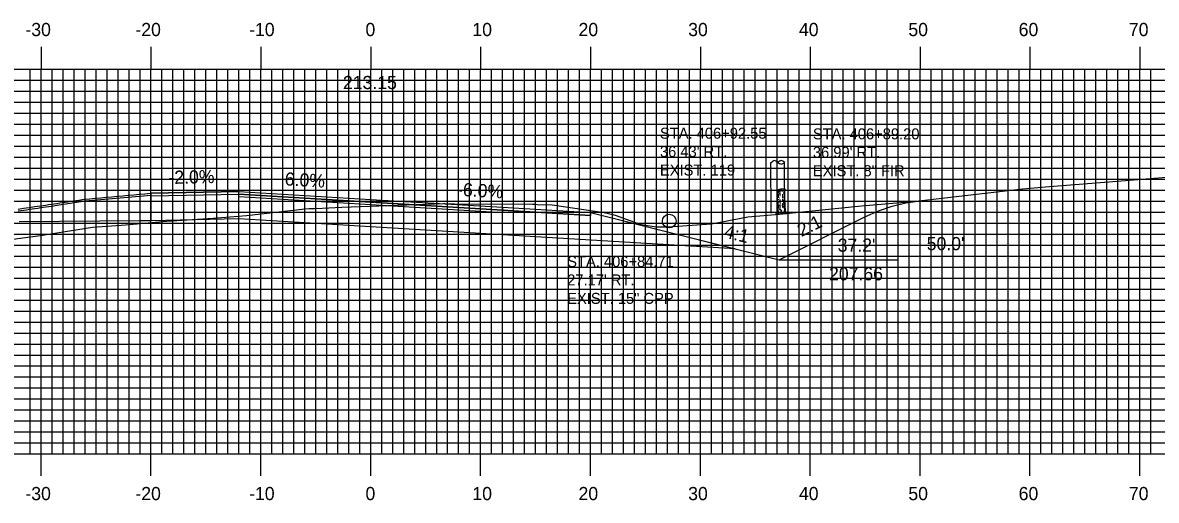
# Model space of a CAD drawing. Extents: x 852135 to 852479, y 364785 to 365005.
# Drawn here: x 852269.5 to 852372.7, y 364904 to 364947.5 of the extents above; entities that cross this region are included whole.
import ezdxf

# ---------------------------------------------------------------- set-up
doc = ezdxf.new("R2010")
doc.units = 0
for name, color, linetype in [('ANNOTATION', 7, 'Continuous'), ('D_Roadway_Centerline', 7, 'Continuous'), ('D_Roadway_Centerline_Text', 7, 'Continuous'), ('D_Roadway_Drive_Paved_LT', 7, 'Continuous'), ('D_Roadway_Drive_SubGrade', 7, 'Continuous'), ('D_Roadway_Edge_Shoulder', 7, 'Continuous'), ('D_Roadway_Edge_TW', 7, 'Continuous'), ('D_Roadway_Pavement', 7, 'Continuous'), ('D_Roadway_SlopeLines', 7, 'Continuous'), ('D_Roadway_SubGrade', 7, 'Continuous'), ('D_Text_Monospaced', 7, 'Continuous'), ('D_Text_Standard', 7, 'Continuous'), ('H_V ANNOTATION', 7, 'Continuous'), ('MAJOR', 7, 'Continuous'), ('MINOR', 7, 'Continuous'), ('PDRAIN', 7, 'Continuous'), ('S_Roadway_Centerline', 7, 'Continuous'), ('S_Trees_Conifer_NonPay', 7, 'Continuous'), ('S_Utilities_Pole_Power', 7, 'Continuous')]:
    doc.layers.add(name, color=color, linetype=linetype)

msp = doc.modelspace()

# ---------------------------------------------------------------- linework, layer by layer
at = {"layer": 'ANNOTATION'}
msp.add_line((852281.22, 364931.94), (852281.22, 364929.44), dxfattribs=at)
at = {"layer": 'D_Roadway_Centerline'}
for points in [[(852281.22, 364931.94), (852289.22, 364932.1), (852301.22, 364931.38), (852313.22, 364930.66), (852321.22, 364930.18), (852334.38, 364926.89), (852338.38, 364925.89), (852346.18, 364929.8), (852347.43, 364930.35), (852348.68, 364930.78), (852349.93, 364931.08), (852351.18, 364931.24)], [(852269.12, 364930.49), (852269.62, 364930.57), (852269.63, 364930.57), (852269.86, 364930.6), (852269.87, 364930.6), (852270.13, 364930.64), (852270.14, 364930.64), (852270.64, 364930.72), (852270.64, 364930.72), (852270.89, 364930.75), (852270.89, 364930.75), (852271.15, 364930.79), (852271.15, 364930.79), (852271.65, 364930.87), (852271.65, 364930.87), (852271.9, 364930.91), (852271.9, 364930.91), (852272.15, 364930.94), (852272.15, 364930.94), (852272.65, 364931.02), (852272.65, 364931.02), (852272.91, 364931.06), (852273.15, 364931.09), (852273.65, 364931.17), (852274.15, 364931.24), (852274.65, 364931.32), (852275.15, 364931.39), (852275.22, 364931.4), (852275.65, 364931.44), (852276.15, 364931.49), (852276.65, 364931.53), (852277.15, 364931.58), (852277.65, 364931.62), (852278.15, 364931.67), (852278.65, 364931.71), (852279.15, 364931.76), (852279.65, 364931.8), (852280.15, 364931.85), (852280.65, 364931.89), (852281.15, 364931.94), (852281.22, 364931.94)]]:
    msp.add_lwpolyline(points, dxfattribs=at)
at = {"layer": 'D_Roadway_Drive_Paved_LT'}
msp.add_lwpolyline([(852269.14, 364930.33), (852269.64, 364930.4), (852269.65, 364930.4), (852269.88, 364930.44), (852269.89, 364930.44), (852270.15, 364930.48), (852270.16, 364930.48), (852270.66, 364930.55), (852270.66, 364930.55), (852270.91, 364930.59), (852270.91, 364930.59), (852271.17, 364930.63), (852271.17, 364930.63), (852271.67, 364930.7), (852271.67, 364930.7), (852271.92, 364930.74), (852271.92, 364930.74), (852272.17, 364930.78), (852272.17, 364930.78), (852272.67, 364930.85), (852272.67, 364930.85), (852275.24, 364931.24), (852281.23, 364931.78)], dxfattribs=at)
at = {"layer": 'D_Roadway_Drive_SubGrade'}
for p, q in [((852280.22, 364929.42), (852269.22, 364929.33)), ((852281.22, 364929.44), (852280.22, 364929.42))]:
    msp.add_line(p, q, dxfattribs=at)
at = {"layer": 'D_Roadway_Edge_Shoulder'}
for points in [[(852289.22, 364932.1), (852281.22, 364931.94), (852281.22, 364931.69), (852289.22, 364931.85)], [(852313.22, 364930.66), (852321.22, 364930.18), (852321.22, 364929.93), (852313.22, 364930.41)]]:
    msp.add_lwpolyline(points, close=True, dxfattribs=at)
at = {"layer": 'D_Roadway_Edge_TW'}
msp.add_lwpolyline([(852289.22, 364931.85), (852289.22, 364932.1), (852301.22, 364931.38), (852313.22, 364930.66), (852313.22, 364930.41), (852301.22, 364931.13)], close=True, dxfattribs=at)
at = {"layer": 'D_Roadway_Pavement'}
msp.add_lwpolyline([(852289.22, 364931.6), (852289.22, 364931.85), (852301.22, 364931.13), (852313.22, 364930.41), (852313.22, 364930.16), (852301.22, 364930.88)], close=True, dxfattribs=at)
at = {"layer": 'D_Roadway_SlopeLines'}
for points in [[(852338.38, 364925.89), (852346.18, 364929.8), (852347.43, 364930.35), (852348.68, 364930.78), (852349.93, 364931.08), (852351.18, 364931.24)], [(852321.22, 364930.18), (852338.38, 364925.89)]]:
    msp.add_lwpolyline(points, dxfattribs=at)
at = {"layer": 'D_Roadway_SubGrade'}
msp.add_lwpolyline([(852289.22, 364929.6), (852281.22, 364929.44), (852281.22, 364931.94), (852281.22, 364931.69), (852289.22, 364931.85), (852301.22, 364931.13), (852313.22, 364930.41), (852321.22, 364929.93), (852321.22, 364930.18), (852334.38, 364926.89), (852313.22, 364928.16), (852301.22, 364928.88)], close=True, dxfattribs=at)
at = {"layer": 'MAJOR'}
for p, q in [((852271.22, 364945.24), (852271.22, 364943.23)), ((852281.22, 364945.24), (852281.22, 364943.23)), ((852291.22, 364945.24), (852291.22, 364943.23)), ((852301.22, 364945.24), (852301.22, 364943.23)), ((852311.22, 364945.24), (852311.22, 364943.23)), ((852321.22, 364945.24), (852321.22, 364943.23)), ((852331.22, 364945.24), (852331.22, 364943.23)), ((852341.22, 364945.24), (852341.22, 364943.23)), ((852351.22, 364945.24), (852351.22, 364943.23)), ((852361.22, 364945.24), (852361.22, 364943.23)), ((852371.22, 364945.24), (852371.22, 364943.23)), ((852161.22, 364943.23), (852441.22, 364943.23)), ((852161.22, 364943.23), (852441.22, 364943.23)), ((852271.22, 364908.23), (852271.22, 364943.23)), ((852281.22, 364908.23), (852281.22, 364943.23)), ((852291.22, 364908.23), (852291.22, 364943.23)), ((852301.22, 364908.23), (852301.22, 364943.23)), ((852311.22, 364908.23), (852311.22, 364943.23)), ((852321.22, 364908.23), (852321.22, 364943.23)), ((852331.22, 364908.23), (852331.22, 364943.23)), ((852341.22, 364908.23), (852341.22, 364943.23)), ((852351.22, 364908.23), (852351.22, 364943.23)), ((852361.22, 364908.23), (852361.22, 364943.23)), ((852371.22, 364908.23), (852371.22, 364943.23)), ((852161.22, 364938.23), (852441.22, 364938.23)), ((852161.22, 364933.23), (852441.22, 364933.23)), ((852161.22, 364928.23), (852441.22, 364928.23)), ((852161.22, 364923.23), (852441.22, 364923.23)), ((852161.22, 364918.23), (852441.22, 364918.23)), ((852161.22, 364913.23), (852441.22, 364913.23)), ((852161.22, 364908.23), (852441.22, 364908.23)), ((852161.22, 364908.23), (852441.22, 364908.23)), ((852271.22, 364906.23), (852271.22, 364908.23)), ((852281.22, 364906.23), (852281.22, 364908.23)), ((852291.22, 364906.23), (852291.22, 364908.23)), ((852301.22, 364906.23), (852301.22, 364908.23)), ((852311.22, 364906.23), (852311.22, 364908.23)), ((852321.22, 364906.23), (852321.22, 364908.23)), ((852331.22, 364906.23), (852331.22, 364908.23)), ((852341.22, 364906.23), (852341.22, 364908.23)), ((852351.22, 364906.23), (852351.22, 364908.23)), ((852361.22, 364906.23), (852361.22, 364908.23)), ((852371.22, 364906.23), (852371.22, 364908.23))]:
    msp.add_line(p, q, dxfattribs=at)
at = {"layer": 'MINOR'}
for p, q in [((852270.22, 364908.23), (852270.22, 364943.23)), ((852272.22, 364908.23), (852272.22, 364943.23)), ((852273.22, 364908.23), (852273.22, 364943.23)), ((852274.22, 364908.23), (852274.22, 364943.23)), ((852275.22, 364908.23), (852275.22, 364943.23)), ((852276.22, 364908.23), (852276.22, 364943.23)), ((852277.22, 364908.23), (852277.22, 364943.23)), ((852278.22, 364908.23), (852278.22, 364943.23)), ((852279.22, 364908.23), (852279.22, 364943.23)), ((852280.22, 364908.23), (852280.22, 364943.23)), ((852282.22, 364908.23), (852282.22, 364943.23)), ((852283.22, 364908.23), (852283.22, 364943.23)), ((852284.22, 364908.23), (852284.22, 364943.23)), ((852285.22, 364908.23), (852285.22, 364943.23)), ((852286.22, 364908.23), (852286.22, 364943.23)), ((852287.22, 364908.23), (852287.22, 364943.23)), ((852288.22, 364908.23), (852288.22, 364943.23)), ((852289.22, 364908.23), (852289.22, 364943.23)), ((852290.22, 364908.23), (852290.22, 364943.23)), ((852292.22, 364908.23), (852292.22, 364943.23)), ((852293.22, 364908.23), (852293.22, 364943.23)), ((852294.22, 364908.23), (852294.22, 364943.23)), ((852295.22, 364908.23), (852295.22, 364943.23)), ((852296.22, 364908.23), (852296.22, 364943.23)), ((852297.22, 364908.23), (852297.22, 364943.23)), ((852298.22, 364908.23), (852298.22, 364943.23)), ((852299.22, 364908.23), (852299.22, 364943.23)), ((852300.22, 364908.23), (852300.22, 364943.23)), ((852302.22, 364908.23), (852302.22, 364943.23)), ((852303.22, 364908.23), (852303.22, 364943.23)), ((852304.22, 364908.23), (852304.22, 364943.23)), ((852305.22, 364908.23), (852305.22, 364943.23)), ((852306.22, 364908.23), (852306.22, 364943.23)), ((852307.22, 364908.23), (852307.22, 364943.23)), ((852308.22, 364908.23), (852308.22, 364943.23)), ((852309.22, 364908.23), (852309.22, 364943.23)), ((852310.22, 364908.23), (852310.22, 364943.23)), ((852312.22, 364908.23), (852312.22, 364943.23)), ((852313.22, 364908.23), (852313.22, 364943.23)), ((852314.22, 364908.23), (852314.22, 364943.23)), ((852315.22, 364908.23), (852315.22, 364943.23)), ((852316.22, 364908.23), (852316.22, 364943.23)), ((852317.22, 364908.23), (852317.22, 364943.23)), ((852318.22, 364908.23), (852318.22, 364943.23)), ((852319.22, 364908.23), (852319.22, 364943.23)), ((852320.22, 364908.23), (852320.22, 364943.23)), ((852322.22, 364908.23), (852322.22, 364943.23)), ((852323.22, 364908.23), (852323.22, 364943.23)), ((852324.22, 364908.23), (852324.22, 364943.23)), ((852325.22, 364908.23), (852325.22, 364943.23)), ((852326.22, 364908.23), (852326.22, 364943.23)), ((852327.22, 364908.23), (852327.22, 364943.23)), ((852328.22, 364908.23), (852328.22, 364943.23)), ((852329.22, 364908.23), (852329.22, 364943.23)), ((852330.22, 364908.23), (852330.22, 364943.23)), ((852332.22, 364908.23), (852332.22, 364943.23)), ((852333.22, 364908.23), (852333.22, 364943.23)), ((852334.22, 364908.23), (852334.22, 364943.23)), ((852335.22, 364908.23), (852335.22, 364943.23)), ((852336.22, 364908.23), (852336.22, 364943.23)), ((852337.22, 364908.23), (852337.22, 364943.23)), ((852338.22, 364908.23), (852338.22, 364943.23)), ((852339.22, 364908.23), (852339.22, 364943.23)), ((852340.22, 364908.23), (852340.22, 364943.23)), ((852342.22, 364908.23), (852342.22, 364943.23)), ((852343.22, 364908.23), (852343.22, 364943.23)), ((852344.22, 364908.23), (852344.22, 364943.23)), ((852345.22, 364908.23), (852345.22, 364943.23)), ((852346.22, 364908.23), (852346.22, 364943.23)), ((852347.22, 364908.23), (852347.22, 364943.23)), ((852348.22, 364908.23), (852348.22, 364943.23)), ((852349.22, 364908.23), (852349.22, 364943.23)), ((852350.22, 364908.23), (852350.22, 364943.23)), ((852352.22, 364908.23), (852352.22, 364943.23)), ((852353.22, 364908.23), (852353.22, 364943.23)), ((852354.22, 364908.23), (852354.22, 364943.23)), ((852355.22, 364908.23), (852355.22, 364943.23)), ((852356.22, 364908.23), (852356.22, 364943.23)), ((852357.22, 364908.23), (852357.22, 364943.23)), ((852358.22, 364908.23), (852358.22, 364943.23)), ((852359.22, 364908.23), (852359.22, 364943.23)), ((852360.22, 364908.23), (852360.22, 364943.23)), ((852362.22, 364908.23), (852362.22, 364943.23)), ((852363.22, 364908.23), (852363.22, 364943.23)), ((852364.22, 364908.23), (852364.22, 364943.23)), ((852365.22, 364908.23), (852365.22, 364943.23)), ((852366.22, 364908.23), (852366.22, 364943.23)), ((852367.22, 364908.23), (852367.22, 364943.23)), ((852368.22, 364908.23), (852368.22, 364943.23)), ((852369.22, 364908.23), (852369.22, 364943.23)), ((852370.22, 364908.23), (852370.22, 364943.23)), ((852372.22, 364908.23), (852372.22, 364943.23)), ((852161.22, 364942.23), (852441.22, 364942.23)), ((852161.22, 364941.23), (852441.22, 364941.23)), ((852161.22, 364940.23), (852441.22, 364940.23)), ((852161.22, 364939.23), (852441.22, 364939.23)), ((852161.22, 364937.23), (852441.22, 364937.23)), ((852161.22, 364936.23), (852441.22, 364936.23)), ((852161.22, 364935.23), (852441.22, 364935.23)), ((852161.22, 364934.23), (852441.22, 364934.23)), ((852161.22, 364932.23), (852441.22, 364932.23)), ((852161.22, 364931.23), (852441.22, 364931.23)), ((852161.22, 364930.23), (852441.22, 364930.23)), ((852161.22, 364929.23), (852441.22, 364929.23)), ((852161.22, 364927.23), (852441.22, 364927.23)), ((852161.22, 364926.23), (852441.22, 364926.23)), ((852161.22, 364925.23), (852441.22, 364925.23)), ((852161.22, 364924.23), (852441.22, 364924.23)), ((852161.22, 364922.23), (852441.22, 364922.23)), ((852161.22, 364921.23), (852441.22, 364921.23)), ((852161.22, 364920.23), (852441.22, 364920.23)), ((852161.22, 364919.23), (852441.22, 364919.23)), ((852161.22, 364917.23), (852441.22, 364917.23)), ((852161.22, 364916.23), (852441.22, 364916.23)), ((852161.22, 364915.23), (852441.22, 364915.23)), ((852161.22, 364914.23), (852441.22, 364914.23)), ((852161.22, 364912.23), (852441.22, 364912.23)), ((852161.22, 364911.23), (852441.22, 364911.23)), ((852161.22, 364910.23), (852441.22, 364910.23)), ((852161.22, 364909.23), (852441.22, 364909.23))]:
    msp.add_line(p, q, dxfattribs=at)
at = {"layer": 'PDRAIN'}
msp.add_line((852338.38, 364925.89), (852349.15, 364925.89), dxfattribs=at)
at = {"layer": 'S_Roadway_Centerline'}
msp.add_lwpolyline([(852256.11, 364926.11), (852270.92, 364928.07), (852271.12, 364928.11), (852271.36, 364928.14), (852271.71, 364928.2), (852275.89, 364928.86), (852278.94, 364929.08), (852282.62, 364929.4), (852286.88, 364929.67), (852289.9, 364929.92), (852295.26, 364930.52), (852295.63, 364930.56), (852296.23, 364930.56), (852298.59, 364930.66), (852307.87, 364931), (852307.95, 364931.01), (852308.83, 364930.98), (852315.94, 364930.95), (852316.13, 364930.96), (852316.17, 364930.95), (852316.36, 364930.91), (852317.74, 364930.9), (852322.45, 364930.19), (852323.25, 364930.02), (852323.57, 364929.93), (852325.81, 364929.09), (852327.24, 364928.9), (852328.26, 364928.9), (852332.23, 364929.17), (852335.55, 364929.81), (852338.41, 364930.04), (852345.87, 364930.79), (852349.1, 364931.08), (852350.59, 364931.18), (852360.55, 364932.35), (852363.01, 364932.56), (852369.15, 364933.04), (852376.64, 364933.64)], dxfattribs=at)
at = {"layer": 'S_Trees_Conifer_NonPay'}
for p, q in [((852338.29, 364932.13), (852338.29, 364931.92)), ((852338.7, 364932.19), (852338.7, 364932.11)), ((852338.27, 364931.03), (852338.27, 364930.93)), ((852338.29, 364931.85), (852338.29, 364931.52)), ((852338.29, 364931.41), (852338.29, 364931.33)), ((852338.29, 364931.21), (852338.29, 364931.1)), ((852338.44, 364932.01), (852338.44, 364931.73)), ((852338.44, 364931.38), (852338.44, 364931.06)), ((852338.48, 364931.02), (852338.48, 364930.95)), ((852338.7, 364931.86), (852338.7, 364931.53)), ((852338.7, 364931.43), (852338.7, 364931.28)), ((852338.7, 364931.05), (852338.7, 364930.82)), ((852338.84, 364931.9), (852338.84, 364931.77)), ((852338.84, 364931.66), (852338.84, 364931.43)), ((852338.84, 364931.34), (852338.84, 364930.96)), ((852338.29, 364930.82), (852338.29, 364930.55)), ((852338.44, 364930.89), (852338.44, 364930.73)), ((852338.44, 364930.67), (852338.44, 364930.54)), ((852338.7, 364930.75), (852338.7, 364930.67)), ((852338.82, 364930.77), (852338.84, 364930.52)), ((852338.9, 364930.54), (852338.96, 364930.55))]:
    msp.add_line(p, q, dxfattribs=at)
for points in [[(852338.21, 364932.16), (852338.21, 364930.45), (852338.14, 364930.19), (852338.02, 364930.16), (852338.23, 364930.14), (852338.39, 364930.08), (852338.6, 364930.14), (852338.87, 364930.09), (852339.07, 364930.1), (852338.92, 364930.2), (852338.85, 364930.35)], [(852338.84, 364932.23), (852338.84, 364932.13), (852338.84, 364931.96)], [(852338.95, 364930.18), (852339.07, 364930.19), (852338.97, 364930.32), (852338.94, 364930.86), (852338.92, 364931.37), (852338.92, 364932.29)], [(852338.23, 364930.14), (852338.32, 364930.25), (852338.34, 364930.37)], [(852338.37, 364930.5), (852338.35, 364930.46), (852338.41, 364930.45), (852338.41, 364930.51)], [(852338.6, 364930.14), (852338.56, 364930.32), (852338.55, 364930.48)], [(852338.56, 364930.37), (852338.63, 364930.36), (852338.64, 364930.41)]]:
    msp.add_lwpolyline(points, dxfattribs=at)
for centre, radius, start, end in [((852338.27, 364932.13), 0.0729, 130.3798, 141.6195), ((852338.23, 364932.16), 0.0263, 141.6195, 160.3798), ((852338.23, 364932.16), 0.0186, 160.3798, 174.3267), ((852338.22, 364932.16), 0.0141, 174.3267, 190.3798), ((852338.22, 364932.16), 0.0141, 190.3798, 206.433), ((852338.23, 364932.17), 0.0186, 206.433, 220.3798), ((852338.23, 364932.17), 0.0263, 220.3798, 239.1402), ((852338.22, 364932.05), 0.0143, 180, 196.0515), ((852338.38, 364932), 0.245, 108.3946, 130.3798), ((852338.25, 364932.21), 0.0729, 239.1402, 250.3798), ((852338.31, 364932.37), 0.245, 250.3798, 272.3651), ((852338.88, 364930.5), 1.83, 100.3798, 108.3946), ((852338.25, 364933.95), 1.83, 272.3651, 280.3798), ((852338.88, 364930.5), 1.83, 92.3651, 100.3798), ((852338.25, 364933.95), 1.83, 280.3798, 288.3946), ((852338.81, 364932.08), 0.245, 70.3798, 92.3651), ((852338.75, 364932.45), 0.245, 288.3946, 310.3798), ((852338.78, 364932.24), 0.245, 291.7653, 300), ((852338.87, 364932.24), 0.0729, 59.1402, 70.3798), ((852338.86, 364932.09), 0.0738, 300, 311.2506), ((852338.9, 364932.28), 0.0263, 40.3798, 59.1402), ((852338.86, 364932.32), 0.0729, 310.3798, 321.6195), ((852338.89, 364932.29), 0.0263, 321.6195, 340.3798), ((852338.9, 364932.05), 0.0267, 311.2506, 330), ((852338.91, 364932.29), 0.0141, 10.3798, 26.433), ((852338.9, 364932.29), 0.0186, 26.433, 40.3798), ((852338.9, 364932.29), 0.0186, 340.3798, 354.3267), ((852338.91, 364932.29), 0.0141, 354.3267, 10.3798), ((852338.9, 364932.05), 0.0189, 330, 343.9485), ((852338.22, 364931.58), 0.0143, 180, 196.0515), ((852338.23, 364931.58), 0.0189, 196.0515, 210), ((852338.23, 364931.59), 0.0267, 210, 228.7494), ((852338.22, 364931.37), 0.0143, 180, 196.0515), ((852338.23, 364931.37), 0.0189, 196.0515, 210), ((852338.23, 364931.38), 0.0267, 210, 228.7494), ((852338.26, 364931.62), 0.0738, 228.7494, 240), ((852338.26, 364931.41), 0.0738, 228.7494, 240), ((852338.35, 364931.77), 0.245, 240, 246.7914), ((852338.35, 364931.56), 0.245, 240, 254.9514), ((852338.35, 364931.98), 0.245, 244.3148, 257.5375), ((852338.35, 364932.24), 0.245, 254.8461, 261.8968), ((852338.35, 364931.77), 0.245, 254.8461, 257.5454), ((852338.35, 364931.34), 0.245, 254.9814, 261.8968), ((852338.56, 364932.85), 1.77, 261.8968, 262.45), ((852338.56, 364933.74), 1.77, 261.8968, 262.605), ((852338.56, 364933.74), 1.77, 264.3267, 266.0499), ((852338.56, 364933.28), 1.77, 265.2285, 266.1325), ((852338.57, 364933.49), 1.77, 265.8991, 267.5962), ((852338.56, 364933.07), 1.77, 266.0429, 268.5525), ((852338.57, 364933.49), 1.77, 272.7221, 274.4847), ((852338.56, 364933.07), 1.77, 274.5361, 277.0026), ((852338.56, 364933.74), 1.77, 276.2449, 278.1032), ((852338.56, 364932.85), 1.77, 276.7966, 278.1032), ((852338.78, 364932.24), 0.245, 278.1032, 284.1859), ((852338.78, 364931.34), 0.245, 278.1032, 284.3207), ((852338.78, 364931.77), 0.245, 284.1859, 300), ((852338.78, 364931.56), 0.245, 292.1924, 300), ((852338.86, 364931.62), 0.0738, 300, 311.2506), ((852338.86, 364931.41), 0.0738, 300, 311.2506), ((852338.9, 364931.8), 0.0267, 311.2506, 330), ((852338.9, 364931.59), 0.0267, 311.2506, 330), ((852338.9, 364931.38), 0.0267, 311.2506, 330), ((852338.9, 364931.8), 0.0189, 330, 343.9485), ((852338.9, 364931.58), 0.0189, 330, 343.9485), ((852338.9, 364931.37), 0.0189, 330, 343.9485), ((852338.22, 364930.93), 0.0143, 180, 196.0515), ((852338.22, 364930.73), 0.0143, 180, 196.0515), ((852338.23, 364930.73), 0.0189, 196.0515, 210), ((852338.23, 364930.73), 0.0267, 210, 228.7494), ((852338.26, 364930.77), 0.0738, 228.7494, 240), ((852338.35, 364930.92), 0.245, 240, 249.1675), ((852338.56, 364932.63), 1.77, 262.2622, 265.0496), ((852338.56, 364932.43), 1.77, 266.0862, 268.2187), ((852338.56, 364932.63), 1.77, 272.6293, 274.5612), ((852338.56, 364932.43), 1.77, 274.2776, 276.3006), ((852338.56, 364932.63), 1.77, 277.63, 278.1032), ((852338.78, 364931.12), 0.245, 278.1032, 294.6056), ((852338.78, 364930.92), 0.245, 284.0684, 300), ((852338.86, 364930.77), 0.0738, 300, 302.05)]:
    msp.add_arc(centre, radius, start, end, dxfattribs=at)
at = {"layer": 'S_Utilities_Pole_Power'}
for p, q in [((852337.65, 364930.13), (852337.64, 364934.75)), ((852337.65, 364934.75), (852337.8, 364934.86)), ((852338.12, 364934.86), (852338.27, 364934.75)), ((852338.43, 364934.86), (852338.27, 364934.75)), ((852338.27, 364934.75), (852338.43, 364934.64)), ((852338.9, 364934.75), (852338.74, 364934.86)), ((852338.74, 364934.64), (852338.9, 364934.75)), ((852338.9, 364930.13), (852338.89, 364934.75))]:
    msp.add_line(p, q, dxfattribs=at)
msp.add_circle((852328.39, 364929.41), 0.625, dxfattribs=at)
for centre, start, end in [((852337.96, 364934.64), 90, 125.2644), ((852337.96, 364934.64), 54.7356, 90), ((852338.58, 364934.64), 90, 125.2644), ((852338.58, 364934.86), 234.7356, 270), ((852338.58, 364934.64), 54.7356, 90), ((852338.58, 364934.86), 270, 305.2644)]:
    msp.add_arc(centre, 0.271, start, end, dxfattribs=at)

# ---------------------------------------------------------------- texts
at = {"layer": 'ANNOTATION'}
for s, rotation, p in [('-2.0%', 1.1458, (852282.82, 364932.78)), ('6.0%', 356.5664, (852293.37, 364932.66)), ('-6.0%', 356.5664, (852309.05, 364931.72)), ('4:1', 345.9638, (852333.31, 364927.93)), ('2:1', 26.5651, (852340.42, 364927.95))]:
    msp.add_text(s, height=1.2, rotation=rotation, dxfattribs=at).set_placement(p)
for s, p in [("37.2'", (852343.72, 364926.62)), ('207.66', (852342.93, 364924.02))]:
    msp.add_text(s, height=1.2, dxfattribs=at).set_placement(p)
at = {"layer": 'D_Roadway_Centerline'}
for s, p in [('C', (852301.21, 364931.38)), ('L', (852301.22, 364931.38))]:
    msp.add_text(s, height=0.0146, dxfattribs=at).set_placement(p)
at = {"layer": 'D_Roadway_Centerline_Text'}
msp.add_text('213.15', height=1.2, dxfattribs=at).set_placement((852298.69, 364941.41))
at = {"layer": 'D_Text_Monospaced'}
for s, p in [('STA. 406+92.55', (852327.54, 364936.9)), ('STA. 406+89.20', (852341.46, 364936.84)), ("36.43' RT.", (852327.54, 364935.23)), ("36.99' RT.", (852341.46, 364935.17)), ('EXIST. 119', (852327.54, 364933.55)), ('EXIST. 8" FIR', (852341.46, 364933.49)), ('STA. 406+84.71', (852319.1, 364925.23)), ("27.17' RT.", (852319.1, 364923.56)), ('EXIST. 15" CPP', (852319.1, 364921.88))]:
    msp.add_text(s, height=1, dxfattribs=at).set_placement(p)
at = {"layer": 'D_Text_Standard'}
msp.add_text("50.0'", height=1.2, dxfattribs=at).set_placement((852351.82, 364926.76))
at = {"layer": 'H_V ANNOTATION'}
for s, p in [('-30', (852269.79, 364946.23)), ('-20', (852279.8, 364946.23)), ('-10', (852290.15, 364946.23)), ('0', (852300.74, 364946.23)), ('10', (852310.47, 364946.23)), ('20', (852320.13, 364946.23)), ('30', (852330.11, 364946.23)), ('40', (852340.19, 364946.23)), ('50', (852350.15, 364946.23)), ('60', (852360.19, 364946.23)), ('70', (852370.22, 364946.23)), ('-30', (852269.79, 364904.03)), ('-20', (852279.8, 364904.03)), ('-10', (852290.15, 364904.03)), ('0', (852300.74, 364904.03)), ('10', (852310.47, 364904.03)), ('20', (852320.13, 364904.03)), ('30', (852330.11, 364904.03)), ('40', (852340.19, 364904.03)), ('50', (852350.15, 364904.03)), ('60', (852360.19, 364904.03)), ('70', (852370.22, 364904.03))]:
    msp.add_text(s, height=1.2, dxfattribs=at).set_placement(p)
at = {"layer": 'S_Roadway_Centerline'}
for s, p in [('L', (852295.62, 364930.55)), ('C', (852295.63, 364930.56))]:
    msp.add_text(s, height=0.0146, dxfattribs=at).set_placement(p)

doc.saveas('drawing.dxf')
